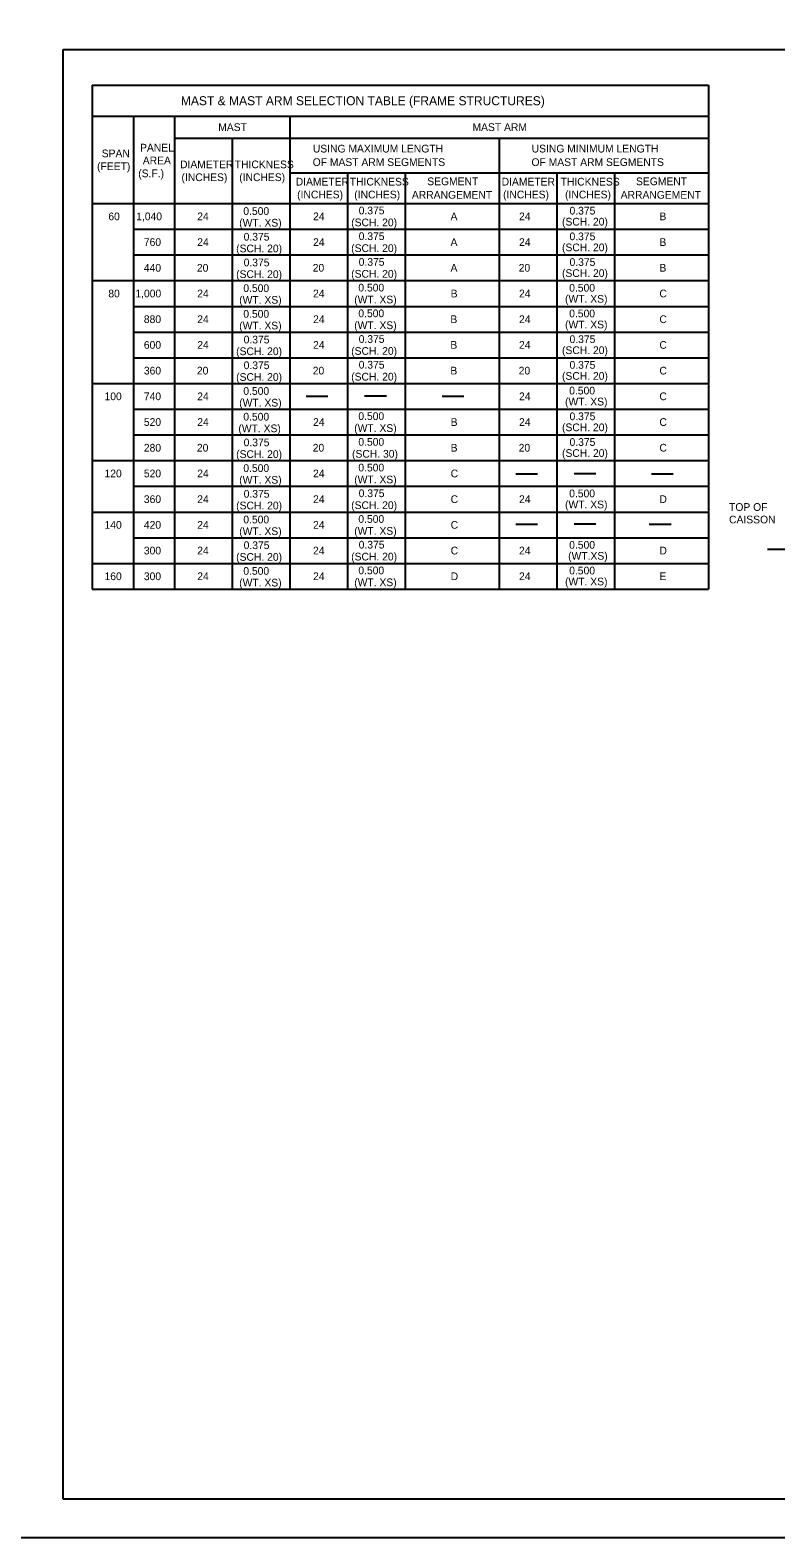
# Model space of a CAD drawing. Extents: x 640117 to 642655, y 297247 to 298435.
# Drawn here: x 640986 to 641275, y 297247 to 297834 of the extents above; entities that cross this region are included whole.
import ezdxf

# ---------------------------------------------------------------- set-up
doc = ezdxf.new("R2010")
doc.units = 0
for name, color, linetype in [('2', 7, 'Continuous'), ('3', 7, 'Continuous'), ('52', 7, 'Continuous'), ('53', 7, 'Continuous'), ('PLT-BNDY', 7, 'Continuous')]:
    doc.layers.add(name, color=color, linetype=linetype)

msp = doc.modelspace()

# ---------------------------------------------------------------- linework, layer by layer
at = {"layer": '2'}
for p, q in [((640998.46, 297262.46), (640998.46, 297826.46)), ((640998.46, 297826.46), (641784.46, 297826.46)), ((641784.46, 297262.46), (640998.46, 297262.46))]:
    msp.add_line(p, q, dxfattribs=at)
at = {"layer": '3'}
for p, q in [((641009.7, 297812.51), (641249.25, 297812.51)), ((641009.7, 297812.51), (641009.7, 297616.51)), ((641249.25, 297812.51), (641249.25, 297616.51)), ((641009.7, 297800.51), (641249.25, 297800.51)), ((641025.7, 297800.51), (641025.7, 297616.51)), ((641041.7, 297800.51), (641041.7, 297616.51)), ((641086.5, 297800.51), (641086.5, 297616.51)), ((641041.7, 297791.98), (641249.25, 297791.98)), ((641064.1, 297791.98), (641064.1, 297616.51)), ((641167.88, 297791.98), (641167.88, 297616.51)), ((641086.5, 297778.51), (641249.25, 297778.51)), ((641108.9, 297778.51), (641108.9, 297616.51)), ((641131.3, 297778.51), (641131.3, 297616.51)), ((641190.28, 297778.51), (641190.28, 297616.51)), ((641212.68, 297778.51), (641212.68, 297616.51)), ((641009.7, 297766.51), (641249.25, 297766.51)), ((641025.7, 297756.51), (641249.25, 297756.51)), ((641025.7, 297746.51), (641249.25, 297746.51)), ((641009.7, 297736.51), (641249.25, 297736.51)), ((641025.7, 297726.51), (641249.25, 297726.51)), ((641025.7, 297716.51), (641249.25, 297716.51)), ((641025.7, 297706.51), (641249.25, 297706.51)), ((641009.7, 297696.51), (641249.25, 297696.51)), ((641092.83, 297691.63), (641101.33, 297691.63)), ((641124.07, 297691.63), (641115.58, 297691.63)), ((641145.66, 297691.63), (641154.16, 297691.63)), ((641025.7, 297686.51), (641249.25, 297686.51)), ((641025.7, 297676.51), (641249.25, 297676.51)), ((641009.7, 297666.51), (641249.25, 297666.51)), ((641174.29, 297661.42), (641182.78, 297661.42)), ((641205.47, 297661.42), (641196.97, 297661.42)), ((641227.06, 297661.42), (641235.55, 297661.42)), ((641025.7, 297656.51), (641249.25, 297656.51)), ((641009.7, 297646.51), (641249.25, 297646.51)), ((641174.29, 297641.73), (641182.78, 297641.73)), ((641205.47, 297641.73), (641196.97, 297641.73)), ((641226.16, 297641.73), (641234.66, 297641.73)), ((641025.7, 297636.51), (641249.25, 297636.51)), ((641009.7, 297626.51), (641249.25, 297626.51)), ((641009.7, 297616.51), (641249.25, 297616.51))]:
    msp.add_line(p, q, dxfattribs=at)
at = {"layer": '52'}
msp.add_line((641306.16, 297631.95), (641272.14, 297631.95), dxfattribs=at)
at = {"layer": 'PLT-BNDY'}
msp.add_lwpolyline([(640958.46, 297841.46), (641799.46, 297841.46), (641799.46, 297247.46), (640958.46, 297247.46)], close=True, dxfattribs=at)

# ---------------------------------------------------------------- texts
at = {"layer": '53'}
for s, height, p in [('MAST & MAST ARM SELECTION TABLE (FRAME STRUCTURES)', 3.5, (641044.14, 297804.76)), ('MAST', 3, (641058.66, 297794.74)), ('MAST ARM', 3, (641157.49, 297794.74)), ('PANEL', 3, (641028.27, 297786.75)), ('SPAN', 3, (641013.39, 297784.51)), ('AREA', 3, (641029.35, 297781.75)), ('OF MAST ARM SEGMENTS', 3, (641095.38, 297781.12)), ('USING MAXIMUM LENGTH', 3, (641095.45, 297786.37)), ('OF MAST ARM SEGMENTS', 3, (641180.42, 297781.12)), ('USING MINIMUM LENGTH', 3, (641180.49, 297786.37)), ('(FEET)', 3, (641011.57, 297779.51)), ('(S.F.)', 3, (641027.57, 297776.75)), ('DIAMETER', 3, (641043.83, 297780.24)), ('(INCHES)', 3, (641044.39, 297775.24)), ('THICKNESS', 3, (641065.09, 297780.24)), ('(INCHES)', 3, (641066.83, 297775.24)), ('DIAMETER', 3, (641088.79, 297773.51)), ('THICKNESS', 3, (641109.8, 297773.51)), ('SEGMENT', 3, (641139.9, 297773.64)), ('DIAMETER', 3, (641168.83, 297773.51)), ('THICKNESS', 3, (641191.74, 297773.51)), ('SEGMENT', 3, (641221.05, 297773.64)), ('(INCHES)', 3, (641089.34, 297768.51)), ('(INCHES)', 3, (641111.54, 297768.51)), ('ARRANGEMENT', 3, (641133.94, 297768.39)), ('(INCHES)', 3, (641169.39, 297768.51)), ('(INCHES)', 3, (641193.48, 297768.51)), ('ARRANGEMENT', 3, (641215.1, 297768.39)), ('60', 3, (641015.95, 297760.01)), ('1,040', 3, (641026.78, 297760.01)), ('24', 3, (641050.51, 297760.01)), ('(WT. XS)', 3, (641066.82, 297757.54)), ('0.500', 3, (641068.42, 297762.09)), ('24', 3, (641095.53, 297760.01)), ('(SCH. 20)', 3, (641110.35, 297757.66)), ('0.375', 3, (641113.26, 297762.3)), ('A', 3, (641148.96, 297760.01)), ('24', 3, (641175.58, 297760.01)), ('(SCH. 20)', 3, (641192.29, 297757.95)), ('0.375', 3, (641195.21, 297762.24)), ('B', 3, (641230.16, 297760.01)), ('0.375', 3, (641068.55, 297752.09)), ('0.375', 3, (641113.26, 297752.3)), ('0.375', 3, (641195.21, 297752.24)), ('760', 3, (641029.76, 297750.01)), ('24', 3, (641050.51, 297750.01)), ('(SCH. 20)', 3, (641065.64, 297747.54)), ('24', 3, (641095.53, 297750.01)), ('(SCH. 20)', 3, (641110.35, 297747.66)), ('A', 3, (641148.96, 297750.01)), ('24', 3, (641175.58, 297750.01)), ('(SCH. 20)', 3, (641192.29, 297747.95)), ('B', 3, (641230.16, 297750.01)), ('440', 3, (641029.76, 297740.01)), ('20', 3, (641050.38, 297740.01)), ('0.375', 3, (641068.55, 297742.09)), ('20', 3, (641095.4, 297740.01)), ('0.375', 3, (641113.26, 297742.3)), ('A', 3, (641148.96, 297740.01)), ('20', 3, (641175.45, 297740.01)), ('0.375', 3, (641195.21, 297742.24)), ('B', 3, (641230.16, 297740.01)), ('(SCH. 20)', 3, (641065.64, 297737.54)), ('(SCH. 20)', 3, (641110.35, 297737.66)), ('(SCH. 20)', 3, (641192.29, 297737.95)), ('80', 3, (641015.95, 297730.01)), ('1,000', 3, (641026.47, 297730.01)), ('24', 3, (641050.51, 297730.01)), ('0.500', 3, (641068.42, 297732.09)), ('24', 3, (641095.53, 297730.01)), ('0.500', 3, (641113.13, 297732.3)), ('B', 3, (641149.01, 297730.01)), ('24', 3, (641175.58, 297730.01)), ('(WT. XS)', 3, (641193.47, 297727.95)), ('0.500', 3, (641195.08, 297732.24)), ('C', 3, (641230.16, 297730.01)), ('C', 3, (641230.16, 297730.01)), ('(WT. XS)', 3, (641066.82, 297727.54)), ('0.500', 3, (641068.42, 297722.09)), ('(WT. XS)', 3, (641111.53, 297727.66)), ('0.500', 3, (641113.13, 297722.3)), ('0.500', 3, (641195.08, 297722.24)), ('880', 3, (641029.76, 297720.01)), ('24', 3, (641050.51, 297720.01)), ('(WT. XS)', 3, (641066.82, 297717.54)), ('24', 3, (641095.53, 297720.01)), ('(WT. XS)', 3, (641111.53, 297717.66)), ('B', 3, (641148.89, 297720.01)), ('24', 3, (641175.58, 297720.01)), ('(WT. XS)', 3, (641193.47, 297717.95)), ('C', 3, (641230.16, 297720.01)), ('0.375', 3, (641068.55, 297712.09)), ('0.375', 3, (641113.26, 297712.3)), ('0.375', 3, (641195.21, 297712.24)), ('600', 3, (641029.76, 297710.01)), ('24', 3, (641050.51, 297710.01)), ('(SCH. 20)', 3, (641065.64, 297707.54)), ('24', 3, (641095.53, 297710.01)), ('(SCH. 20)', 3, (641110.35, 297707.66)), ('B', 3, (641148.89, 297710.01)), ('24', 3, (641175.58, 297710.01)), ('(SCH. 20)', 3, (641192.29, 297707.95)), ('C', 3, (641230.16, 297710.01)), ('360', 3, (641029.76, 297700.01)), ('20', 3, (641050.38, 297700.01)), ('0.375', 3, (641068.55, 297702.09)), ('20', 3, (641095.4, 297700.01)), ('0.375', 3, (641113.26, 297702.3)), ('B', 3, (641148.89, 297700.01)), ('20', 3, (641175.45, 297700.01)), ('0.375', 3, (641195.21, 297702.24)), ('C', 3, (641230.16, 297700.01)), ('(SCH. 20)', 3, (641065.64, 297697.54)), ('(SCH. 20)', 3, (641110.35, 297697.66)), ('(SCH. 20)', 3, (641192.29, 297697.95)), ('100', 3, (641014.47, 297690.01)), ('740', 3, (641029.76, 297690.01)), ('24', 3, (641050.51, 297690.01)), ('(WT. XS)', 3, (641066.82, 297687.54)), ('0.500', 3, (641068.42, 297692.09)), ('24', 3, (641175.58, 297690.01)), ('(WT. XS)', 3, (641193.47, 297687.95)), ('0.500', 3, (641195.08, 297692.24)), ('C', 3, (641230.16, 297690.01)), ('0.500', 3, (641068.42, 297682.09)), ('0.500', 3, (641113.13, 297682.3)), ('0.375', 3, (641195.21, 297682.24)), ('520', 3, (641029.76, 297680.01)), ('24', 3, (641050.51, 297680.01)), ('(WT. XS)', 3, (641066.5, 297677.54)), ('24', 3, (641095.53, 297680.01)), ('(WT. XS)', 3, (641111.53, 297677.66)), ('B', 3, (641149.01, 297680.01)), ('24', 3, (641175.58, 297680.01)), ('(SCH. 20)', 3, (641192.29, 297677.95)), ('C', 3, (641230.16, 297680.01)), ('280', 3, (641029.76, 297670.01)), ('20', 3, (641050.38, 297670.01)), ('0.375', 3, (641068.55, 297672.09)), ('20', 3, (641095.4, 297670.01)), ('0.500', 3, (641113.13, 297672.3)), ('B', 3, (641149.01, 297670.01)), ('20', 3, (641175.45, 297670.01)), ('0.375', 3, (641195.21, 297672.24)), ('C', 3, (641230.16, 297670.01)), ('(SCH. 20)', 3, (641065.64, 297667.54)), ('(SCH. 30)', 3, (641110.68, 297667.66)), ('(SCH. 20)', 3, (641192.29, 297667.95)), ('120', 3, (641014.47, 297660.01)), ('520', 3, (641029.76, 297660.01)), ('24', 3, (641050.51, 297660.01)), ('(WT. XS)', 3, (641066.82, 297657.54)), ('0.500', 3, (641068.42, 297662.09)), ('24', 3, (641095.53, 297660.01)), ('(WT. XS)', 3, (641111.53, 297657.66)), ('0.500', 3, (641113.13, 297662.3)), ('C', 3, (641149.01, 297660.01)), ('0.375', 3, (641068.55, 297652.09)), ('0.375', 3, (641113.26, 297652.3)), ('0.500', 3, (641195.08, 297652.24)), ('360', 3, (641029.76, 297650.01)), ('24', 3, (641050.51, 297650.01)), ('(SCH. 20)', 3, (641065.64, 297647.54)), ('24', 3, (641095.53, 297650.01)), ('(SCH. 20)', 3, (641110.35, 297647.66)), ('C', 3, (641149.01, 297650.01)), ('24', 3, (641175.58, 297650.01)), ('(WT. XS)', 3, (641193.47, 297647.95)), ('D', 3, (641230.16, 297650.01)), ('TOP OF', 3, (641257.22, 297646.96)), ('140', 3, (641014.47, 297640.01)), ('420', 3, (641029.76, 297640.01)), ('24', 3, (641050.51, 297640.01)), ('0.500', 3, (641068.42, 297642.09)), ('24', 3, (641095.53, 297640.01)), ('0.500', 3, (641113.13, 297642.3)), ('C', 3, (641149.01, 297640.01)), ('CAISSON', 3, (641257.22, 297642.09)), ('(WT. XS)', 3, (641066.82, 297637.54)), ('(WT. XS)', 3, (641111.53, 297637.66)), ('300', 3, (641029.76, 297630.01)), ('24', 3, (641050.51, 297630.01)), ('0.375', 3, (641068.55, 297632.09)), ('24', 3, (641095.53, 297630.01)), ('0.375', 3, (641113.26, 297632.3)), ('C', 3, (641149.01, 297630.01)), ('24', 3, (641175.58, 297630.01)), ('0.500', 3, (641195.08, 297632.24)), ('D', 3, (641230.16, 297630.01)), ('(SCH. 20)', 3, (641065.64, 297627.54)), ('(SCH. 20)', 3, (641110.35, 297627.66)), ('0.500', 3, (641113.13, 297622.3)), ('(WT.XS)', 3, (641194.67, 297627.95)), ('160', 3, (641014.47, 297620.01)), ('300', 3, (641029.76, 297620.01)), ('24', 3, (641050.51, 297620.01)), ('(WT. XS)', 3, (641066.82, 297617.54)), ('0.500', 3, (641068.42, 297622.09)), ('24', 3, (641095.53, 297620.01)), ('(WT. XS)', 3, (641111.53, 297617.66)), ('D', 3, (641149.01, 297620.01)), ('24', 3, (641175.58, 297620.01)), ('(WT. XS)', 3, (641193.47, 297617.95)), ('0.500', 3, (641195.08, 297622.24)), ('E', 3, (641230.17, 297620.01))]:
    msp.add_text(s, height=height, dxfattribs=at).set_placement(p)

doc.saveas('drawing.dxf')
